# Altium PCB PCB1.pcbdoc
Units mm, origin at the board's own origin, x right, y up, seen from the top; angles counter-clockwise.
Board outline 34.96 x 25.84 mm, 2 copper layers (Top Layer, Bottom Layer); 5 components, 0 nets, 65 pads, 0 vias.
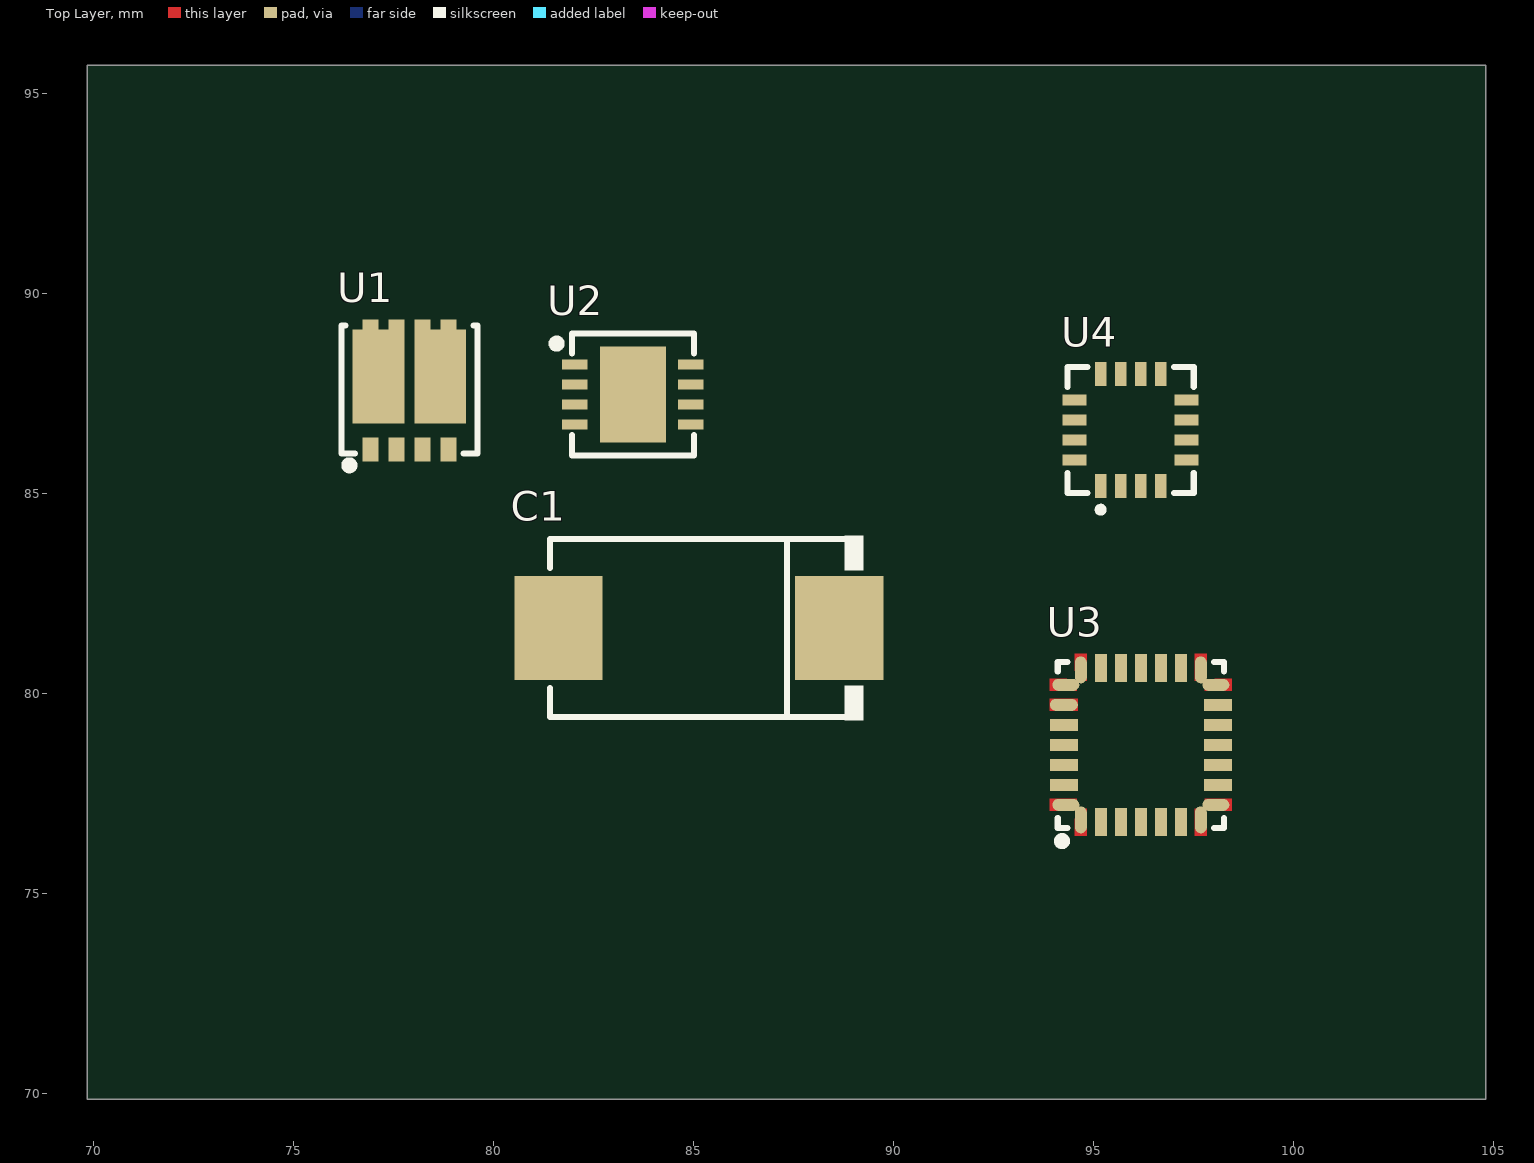
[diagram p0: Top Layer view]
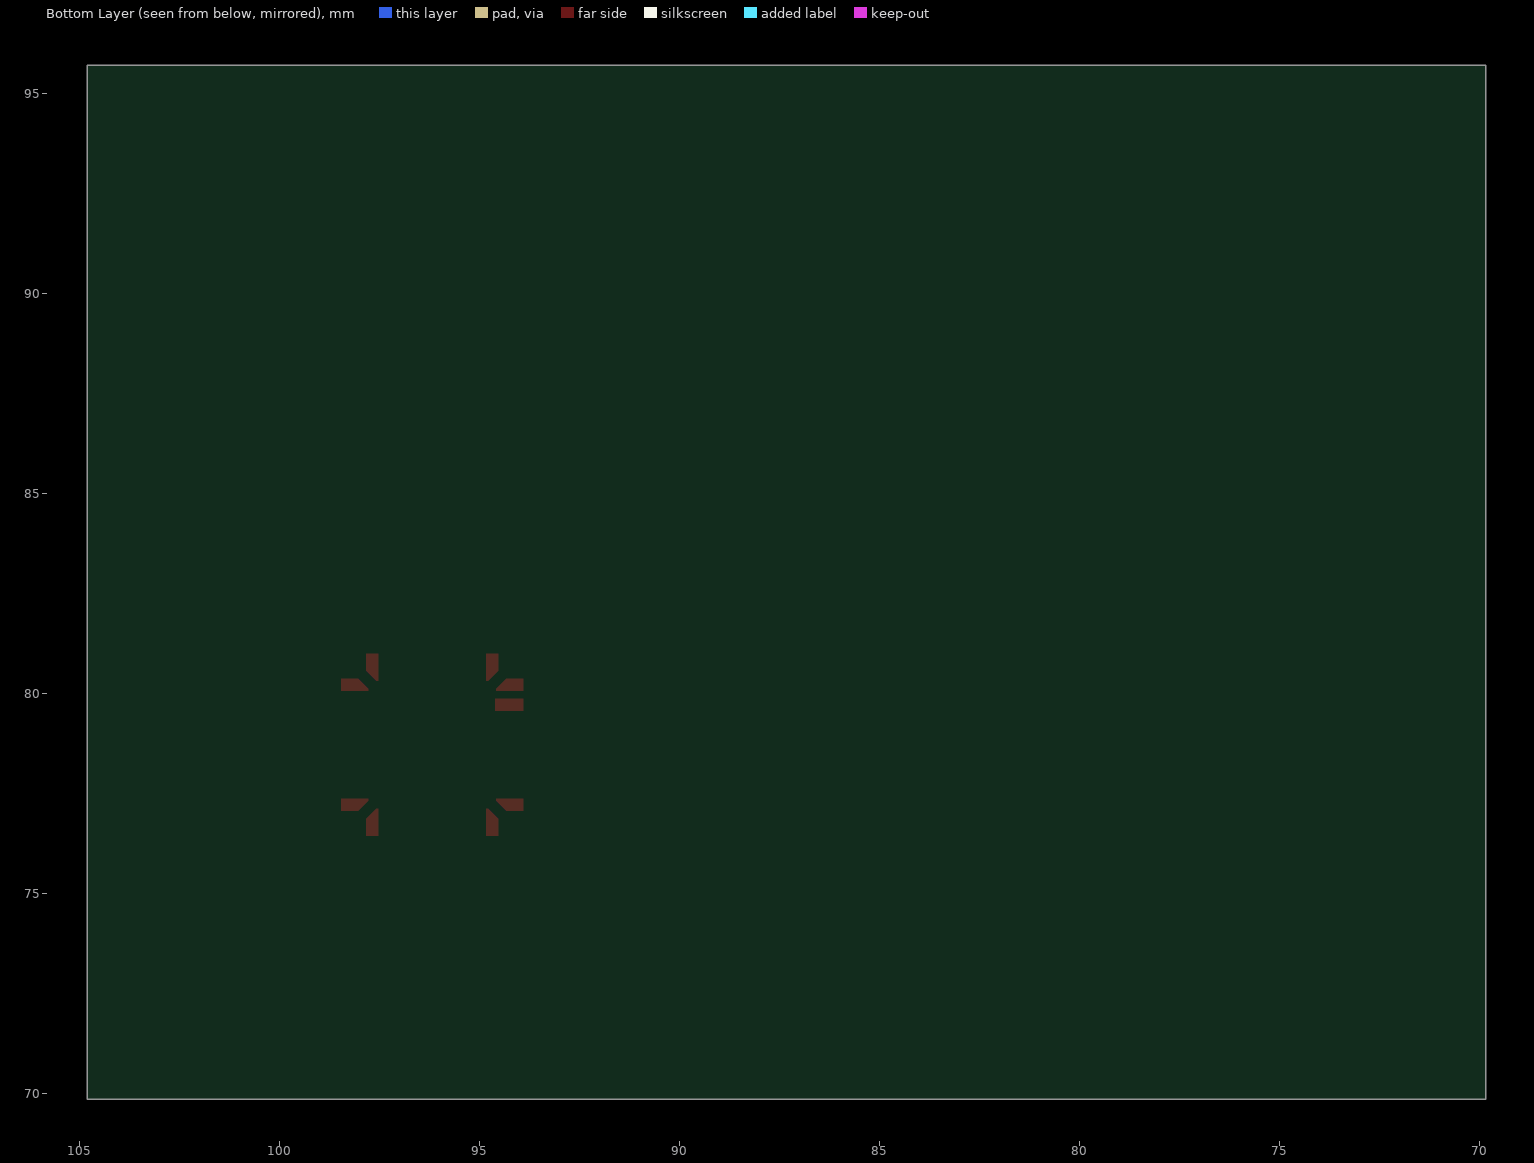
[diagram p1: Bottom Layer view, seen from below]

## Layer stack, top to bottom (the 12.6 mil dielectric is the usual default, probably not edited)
Top Layer: signal copper (thickness not stored)
Dielectric: dielectric 0.32, FR-4, Dk 4.8
Bottom Layer: signal copper (thickness not stored)

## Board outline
104.813,69.85 69.85,69.85 69.85,95.695 104.813,95.695

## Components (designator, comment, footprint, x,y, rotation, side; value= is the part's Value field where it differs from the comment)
C1 "EEFCX0G221YR" CAP-SMD_L7.3-W4.3-R-RD 85.139,81.626 r0 top
U1 "WSD4066DN" DFN-8_L3.2-W3.1-P0.65-LS3.4-BL-EP 77.9,87.595 r0 top
U2 "NCP81155MNTXG" DFN-8_L3.0-W3.0-P0.50-TL-EP 83.488,87.468 r0 top
U3 "STM32G031G8U6" UFQFPN-28_L4.0-W4.0-P0.50-BL 96.188,78.705 r0 top
U4 "IST8310" LGA-16_L3.0-W3.0-P0.5-BL 95.934,86.579 r0 top

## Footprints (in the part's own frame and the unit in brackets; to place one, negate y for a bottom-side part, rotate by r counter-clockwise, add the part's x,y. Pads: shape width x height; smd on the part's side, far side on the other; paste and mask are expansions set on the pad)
CAP-SMD_L7.3-W4.3-R-RD [mm]
  rect 2.207x2.592 smd: 1(3.511,0) 2(-3.511,0)
  silkscreen extent -3.73,-2.3 4.11,2.3
DFN-8_L3.0-W3.0-P0.50-TL-EP [mm]
  rect 0.63x0.25 smd: 1(-1.45,0.75) 2(-1.45,0.25) 3(-1.45,-0.25) 4(-1.45,-0.75) 5(1.45,-0.75) 6(1.45,-0.25) 7(1.45,0.25) 8(1.45,0.75)
  rect 1.65x2.4 smd: 9(0,0)
  silkscreen extent -2,-1.52 1.52,1.52
DFN-8_L3.2-W3.1-P0.65-LS3.4-BL-EP [mm]
  rect 0.4x0.6 smd: 1(-0.975,-1.5) 2(-0.325,-1.5) 3(0.325,-1.5) 4(0.975,-1.5)
  rect 0.4x0.5 smd: 5(0.975,1.5) 6(0.325,1.5) 7(-0.325,1.5) 8(-0.975,1.5)
  rect 1.29x2.35 smd: 9(-0.77,0.325) 10(0.77,0.325)
  silkscreen extent -1.7,-2 1.7,1.6
LGA-16_L3.0-W3.0-P0.5-BL [mm]
  rect 0.28x0.6 smd: 1(-0.75,-1.4) 2(-0.25,-1.4) 3(0.25,-1.4) 4(0.75,-1.4) 9(0.75,1.4) 10(0.25,1.4) 11(-0.25,1.4) 12(-0.75,1.4)
  rect 0.6x0.28 smd: 5(1.4,-0.75) 6(1.4,-0.25) 7(1.4,0.25) 8(1.4,0.75) 13(-1.4,0.75) 14(-1.4,0.25) 15(-1.4,-0.25) 16(-1.4,-0.75)
  silkscreen extent -1.58,-2.07 1.58,1.58
UFQFPN-28_L4.0-W4.0-P0.50-BL [mm]
  oval 0.3x0.675 smd: 1(-1.5,-1.875) 7(1.5,-1.875) 15(1.5,1.875) 21(-1.5,1.875)
  rect 0.3x0.7 smd: 2(-1,-1.925) 3(-0.5,-1.925) 4(0,-1.925) 5(0.5,-1.925) 6(1,-1.925) 16(1,1.925) 17(0.5,1.925) 18(0,1.925) 19(-0.5,1.925) 20(-1,1.925)
  oval 0.675x0.3 smd: 8(1.875,-1.5) 14(1.875,1.5) 22(-1.875,1.5) 28(-1.875,-1.5)
  rect 0.7x0.3 smd: 9(1.925,-1) 10(1.925,-0.5) 11(1.925,0) 12(1.925,0.5) 13(1.925,1) 24(-1.925,0.5) 25(-1.925,0) 26(-1.925,-0.5) 27(-1.925,-1)
  oval 0.7x0.3 smd: 23(-1.925,1)
  Top Layer region: -2.275,1.15 -1.575,1.15 -1.575,0.85 -2.275,0.85
  Top Layer region: 1.85,1.65 2.275,1.65 2.275,1.35 1.6,1.35 1.6,1.4
  Top Layer region: 1.65,1.85 1.65,2.275 1.35,2.275 1.35,1.6 1.4,1.6
  Top Layer region: -1.85,1.65 -2.275,1.65 -2.275,1.35 -1.6,1.35 -1.6,1.4
  Top Layer region: -1.65,1.85 -1.65,2.275 -1.35,2.275 -1.35,1.6 -1.4,1.6
  Top Layer region: -1.65,-1.85 -1.65,-2.275 -1.35,-2.275 -1.35,-1.6 -1.4,-1.6
  Top Layer region: -1.85,-1.65 -2.275,-1.65 -2.275,-1.35 -1.6,-1.35 -1.6,-1.4
  Top Layer region: 1.85,-1.65 2.275,-1.65 2.275,-1.35 1.6,-1.35 1.6,-1.4
  Top Layer region: 1.65,-1.85 1.65,-2.275 1.35,-2.275 1.35,-1.6 1.4,-1.6
  silkscreen extent -2.08,-2.5 2.08,2.08

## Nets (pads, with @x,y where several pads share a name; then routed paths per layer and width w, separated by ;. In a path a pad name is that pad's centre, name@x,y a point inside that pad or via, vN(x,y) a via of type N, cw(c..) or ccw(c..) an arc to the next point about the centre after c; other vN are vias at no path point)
pads on no net: C1.1 C1.2 U1.1 U1.2 U1.3 U1.4 U1.5 U1.6 U1.7 U1.8 U1.9 U1.10 U2.1 U2.2 U2.3 U2.4 U2.5 U2.6 U2.7 U2.8 U2.9 U3.1 U3.2 U3.3 U3.4 U3.5 U3.6 U3.7 U3.8 U3.9 U3.10 U3.11 U3.12 U3.13 U3.14 U3.15 U3.16 U3.17 U3.18 U3.19 U3.20 U3.21 U3.22 U3.23 U3.24 U3.25 U3.26 U3.27 U3.28 U4.1 U4.2 U4.3 U4.4 U4.5 U4.6 U4.7 U4.8 U4.9 U4.10 U4.11 U4.12 U4.13 U4.14 U4.15 U4.16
